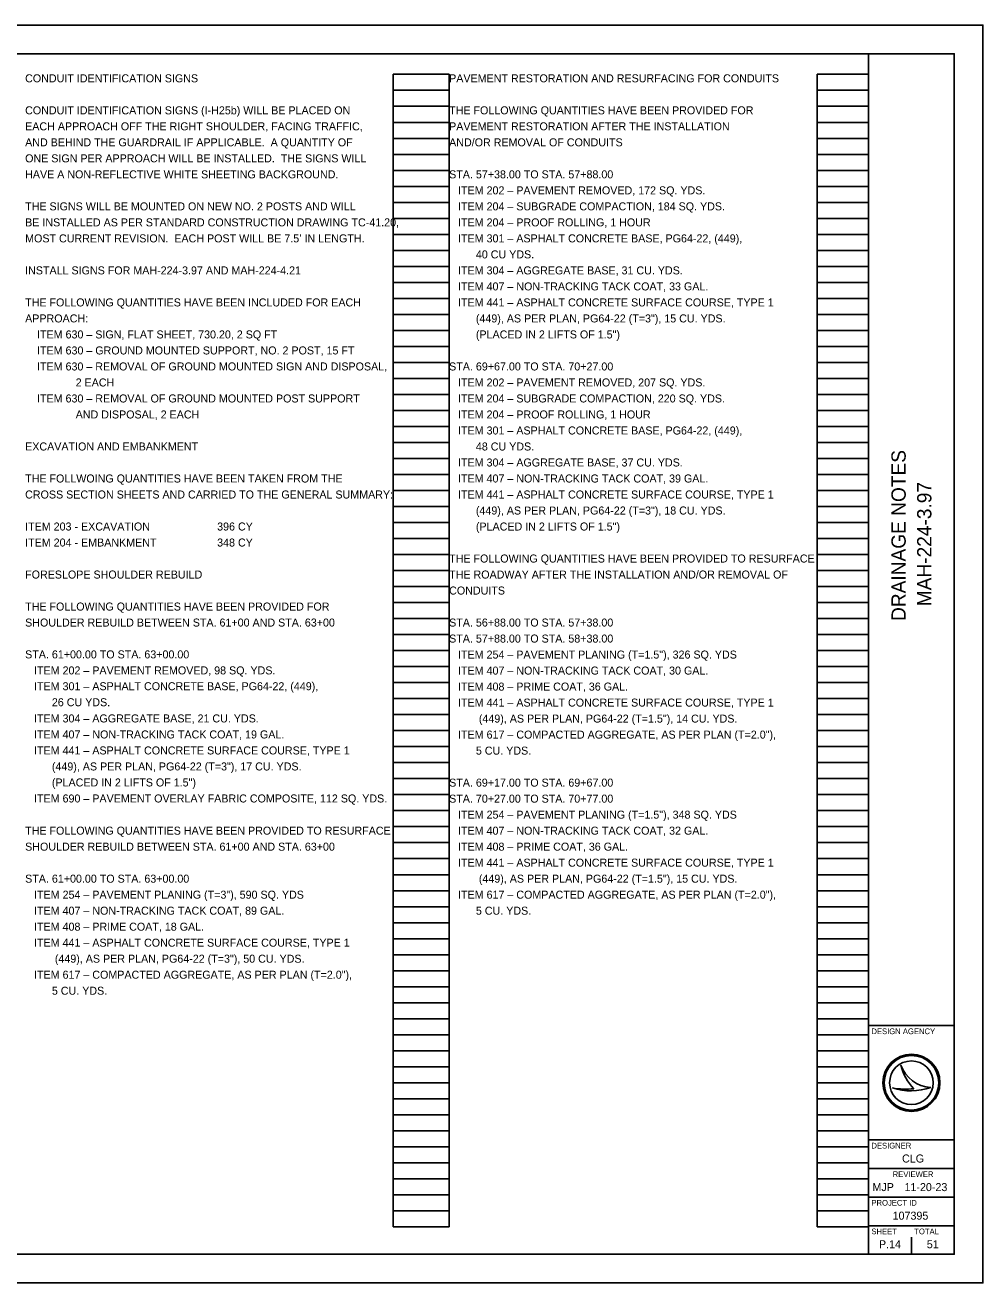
# Model space of a CAD drawing. Extents: x 0 to 34, y 0 to 22.
# Drawn here: x 17.24 to 34, y 0 to 22 of the extents above; entities that cross this region are included whole.
import ezdxf

# ---------------------------------------------------------------- set-up
doc = ezdxf.new("R2010")
doc.units = 0
for name, color, linetype in [('SH_Border', 7, 'Continuous'), ('SH_Cut_Line', 7, 'Continuous'), ('SH_Data', 7, 'Continuous'), ('SH_Text', 7, 'Continuous')]:
    doc.layers.add(name, color=color, linetype=linetype)

msp = doc.modelspace()

# ---------------------------------------------------------------- linework, layer by layer
at = {"layer": 'SH_Border'}
for p, q in [((32, 0.5), (32, 21.5)), ((32, 4.5), (33.5, 4.5)), ((32, 2.5), (33.5, 2.5)), ((32, 2), (33.5, 2)), ((32, 1.5), (33.5, 1.5)), ((32, 1), (33.5, 1))]:
    msp.add_line(p, q, dxfattribs=at)
msp.add_lwpolyline([(1.5, 21.5), (33.5, 21.5), (33.5, 0.5), (1.5, 0.5)], close=True, dxfattribs=at)
at = {"layer": 'SH_Cut_Line'}
msp.add_lwpolyline([(0, 0), (34, 0), (34, 22), (0, 22)], close=True, dxfattribs=at)
at = {"layer": 'SH_Data'}
for p, q in [((23.68, 0.98), (23.68, 21.14)), ((23.68, 21.14), (24.66, 21.14)), ((24.66, 0.98), (24.66, 21.14)), ((31.1, 0.98), (31.1, 21.14)), ((31.1, 21.14), (32, 21.14)), ((32, 0.98), (32, 21.14)), ((23.68, 20.86), (24.66, 20.86)), ((31.1, 20.86), (32, 20.86)), ((23.68, 20.58), (24.66, 20.58)), ((31.1, 20.58), (32, 20.58)), ((23.68, 20.3), (24.66, 20.3)), ((31.1, 20.3), (32, 20.3)), ((23.68, 20.02), (24.66, 20.02)), ((31.1, 20.02), (32, 20.02)), ((23.68, 19.74), (24.66, 19.74)), ((31.1, 19.74), (32, 19.74)), ((23.68, 19.46), (24.66, 19.46)), ((31.1, 19.46), (32, 19.46)), ((23.68, 19.18), (24.66, 19.18)), ((31.1, 19.18), (32, 19.18)), ((23.68, 18.9), (24.66, 18.9)), ((31.1, 18.9), (32, 18.9)), ((23.68, 18.62), (24.66, 18.62)), ((31.1, 18.62), (32, 18.62)), ((23.68, 18.34), (24.66, 18.34)), ((31.1, 18.34), (32, 18.34)), ((23.68, 18.06), (24.66, 18.06)), ((31.1, 18.06), (32, 18.06)), ((23.68, 17.78), (24.66, 17.78)), ((31.1, 17.78), (32, 17.78)), ((23.68, 17.5), (24.66, 17.5)), ((31.1, 17.5), (32, 17.5)), ((23.68, 17.22), (24.66, 17.22)), ((31.1, 17.22), (32, 17.22)), ((23.68, 16.94), (24.66, 16.94)), ((31.1, 16.94), (32, 16.94)), ((23.68, 16.66), (24.66, 16.66)), ((31.1, 16.66), (32, 16.66)), ((23.68, 16.38), (24.66, 16.38)), ((31.1, 16.38), (32, 16.38)), ((23.68, 16.1), (24.66, 16.1)), ((31.1, 16.1), (32, 16.1)), ((23.68, 15.82), (24.66, 15.82)), ((31.1, 15.82), (32, 15.82)), ((23.68, 15.54), (24.66, 15.54)), ((31.1, 15.54), (32, 15.54)), ((23.68, 15.26), (24.66, 15.26)), ((31.1, 15.26), (32, 15.26)), ((23.68, 14.98), (24.66, 14.98)), ((31.1, 14.98), (32, 14.98)), ((23.68, 14.7), (24.66, 14.7)), ((31.1, 14.7), (32, 14.7)), ((23.68, 14.42), (24.66, 14.42)), ((31.1, 14.42), (32, 14.42)), ((23.68, 14.14), (24.66, 14.14)), ((31.1, 14.14), (32, 14.14)), ((23.68, 13.86), (24.66, 13.86)), ((31.1, 13.86), (32, 13.86)), ((23.68, 13.58), (24.66, 13.58)), ((31.1, 13.58), (32, 13.58)), ((23.68, 13.3), (24.66, 13.3)), ((31.1, 13.3), (32, 13.3)), ((23.68, 13.02), (24.66, 13.02)), ((31.1, 13.02), (32, 13.02)), ((23.68, 12.74), (24.66, 12.74)), ((31.1, 12.74), (32, 12.74)), ((23.68, 12.46), (24.66, 12.46)), ((31.1, 12.46), (32, 12.46)), ((23.68, 12.18), (24.66, 12.18)), ((31.1, 12.18), (32, 12.18)), ((23.68, 11.9), (24.66, 11.9)), ((31.1, 11.9), (32, 11.9)), ((23.68, 11.62), (24.66, 11.62)), ((31.1, 11.62), (32, 11.62)), ((23.68, 11.34), (24.66, 11.34)), ((31.1, 11.34), (32, 11.34)), ((23.68, 11.06), (24.66, 11.06)), ((31.1, 11.06), (32, 11.06)), ((23.68, 10.78), (24.66, 10.78)), ((31.1, 10.78), (32, 10.78)), ((23.68, 10.5), (24.66, 10.5)), ((31.1, 10.5), (32, 10.5)), ((23.68, 10.22), (24.66, 10.22)), ((31.1, 10.22), (32, 10.22)), ((23.68, 9.94), (24.66, 9.94)), ((31.1, 9.94), (32, 9.94)), ((23.68, 9.66), (24.66, 9.66)), ((31.1, 9.66), (32, 9.66)), ((23.68, 9.38), (24.66, 9.38)), ((31.1, 9.38), (32, 9.38)), ((23.68, 9.1), (24.66, 9.1)), ((31.1, 9.1), (32, 9.1)), ((23.68, 8.82), (24.66, 8.82)), ((31.1, 8.82), (32, 8.82)), ((23.68, 8.54), (24.66, 8.54)), ((31.1, 8.54), (32, 8.54)), ((23.68, 8.26), (24.66, 8.26)), ((31.1, 8.26), (32, 8.26)), ((23.68, 7.98), (24.66, 7.98)), ((31.1, 7.98), (32, 7.98)), ((23.68, 7.7), (24.66, 7.7)), ((31.1, 7.7), (32, 7.7)), ((23.68, 7.42), (24.66, 7.42)), ((31.1, 7.42), (32, 7.42)), ((23.68, 7.14), (24.66, 7.14)), ((31.1, 7.14), (32, 7.14)), ((23.68, 6.86), (24.66, 6.86)), ((31.1, 6.86), (32, 6.86)), ((23.68, 6.58), (24.66, 6.58)), ((31.1, 6.58), (32, 6.58)), ((23.68, 6.3), (24.66, 6.3)), ((31.1, 6.3), (32, 6.3)), ((23.68, 6.02), (24.66, 6.02)), ((31.1, 6.02), (32, 6.02)), ((23.68, 5.74), (24.66, 5.74)), ((31.1, 5.74), (32, 5.74)), ((23.68, 5.46), (24.66, 5.46)), ((31.1, 5.46), (32, 5.46)), ((23.68, 5.18), (24.66, 5.18)), ((31.1, 5.18), (32, 5.18)), ((23.68, 4.9), (24.66, 4.9)), ((31.1, 4.9), (32, 4.9)), ((23.68, 4.62), (24.66, 4.62)), ((31.1, 4.62), (32, 4.62)), ((23.68, 4.34), (24.66, 4.34)), ((31.1, 4.34), (32, 4.34)), ((23.68, 4.06), (24.66, 4.06)), ((31.1, 4.06), (32, 4.06)), ((23.68, 3.78), (24.66, 3.78)), ((31.1, 3.78), (32, 3.78)), ((32.567, 3.81), (32.567, 3.81)), ((23.68, 3.5), (24.66, 3.5)), ((31.1, 3.5), (32, 3.5)), ((32.417, 3.41), (32.417, 3.41)), ((32.75, 3.5), (32.75, 3.5)), ((33.087, 3.419), (33.087, 3.419)), ((23.68, 3.22), (24.66, 3.22)), ((31.1, 3.22), (32, 3.22)), ((23.68, 2.94), (24.66, 2.94)), ((31.1, 2.94), (32, 2.94)), ((23.68, 2.66), (24.66, 2.66)), ((31.1, 2.66), (32, 2.66)), ((23.68, 2.38), (24.66, 2.38)), ((31.1, 2.38), (32, 2.38)), ((23.68, 2.1), (24.66, 2.1)), ((31.1, 2.1), (32, 2.1)), ((23.68, 1.82), (24.66, 1.82)), ((31.1, 1.82), (32, 1.82)), ((23.68, 1.54), (24.66, 1.54)), ((31.1, 1.54), (32, 1.54)), ((23.68, 1.26), (24.66, 1.26)), ((31.1, 1.26), (32, 1.26)), ((23.68, 0.98), (24.66, 0.98)), ((31.1, 0.98), (32, 0.98)), ((32.375, 0.675), (32.375, 0.675)), ((32.75, 0.5), (32.75, 0.8))]:
    msp.add_line(p, q, dxfattribs=at)
for radius in [0.5, 0.477, 0.477, 0.382]:
    msp.add_circle((32.75, 3.5), radius, dxfattribs=at)
for centre, radius, start, end in [((33.116, 3.998), 0.58, 198.9257, 198.9319), ((33.347, 3.97), 0.796, 191.6379, 191.6421), ((33.116, 3.998), 0.58, 198.9319, 267.1657), ((33.347, 3.97), 0.796, 191.6421, 226.0947), ((32.739, 4.37), 1.013, 251.4576, 290.0832), ((32.648, 4.654), 1.266, 259.4964, 259.4995), ((32.739, 4.37), 1.013, 251.4527, 251.4576), ((32.648, 4.654), 1.266, 259.4995, 276.6672)]:
    msp.add_arc(centre, radius, start, end, dxfattribs=at)

# ---------------------------------------------------------------- texts
for s, p in [('DRAINAGE NOTES', (32.65, 11.578)), ('MAH-224-3.97', (33.1, 11.835))]:
    msp.add_text(s, height=0.25, rotation=90, dxfattribs=at).set_placement(p)
for s, height, p in [('DESIGN AGENCY', 0.1, (32.05, 4.35)), ('DESIGNER', 0.1, (32.05, 2.35)), ('CLG', 0.14, (32.586, 2.105)), ('REVIEWER', 0.1, (32.422, 1.85)), ('MJP', 0.14, (32.068, 1.605)), ('11-20-23', 0.14, (32.629, 1.605)), ('PROJECT ID', 0.1, (32.05, 1.35)), ('107395', 0.14, (32.421, 1.105)), ('SHEET', 0.1, (32.05, 0.85)), ('TOTAL', 0.1, (32.8, 0.85)), ('P.14', 0.14, (32.182, 0.605)), ('51', 0.14, (33.019, 0.605))]:
    msp.add_text(s, height=height, dxfattribs=at).set_placement(p)
at = {"layer": 'SH_Text'}
for s, p in [('CONDUIT IDENTIFICATION SIGNS', (17.24, 21)), ('PAVEMENT RESTORATION AND RESURFACING FOR CONDUITS', (24.66, 21)), ('CONDUIT IDENTIFICATION SIGNS (I-H25b) WILL BE PLACED ON', (17.24, 20.44)), ('THE FOLLOWING QUANTITIES HAVE BEEN PROVIDED FOR', (24.66, 20.44)), ('EACH APPROACH OFF THE RIGHT SHOULDER, FACING TRAFFIC,', (17.24, 20.16)), ('PAVEMENT RESTORATION AFTER THE INSTALLATION', (24.66, 20.16)), ('AND BEHIND THE GUARDRAIL IF APPLICABLE.  A QUANTITY OF', (17.24, 19.88)), ('AND/OR REMOVAL OF CONDUITS', (24.66, 19.88)), ('ONE SIGN PER APPROACH WILL BE INSTALLED.  THE SIGNS WILL', (17.24, 19.6)), ('HAVE A NON-REFLECTIVE WHITE SHEETING BACKGROUND.', (17.24, 19.32)), ('STA. 57+38.00 TO STA. 57+88.00', (24.66, 19.32)), ('   ITEM 202 – PAVEMENT REMOVED, 172 SQ. YDS.', (24.66, 19.04)), ('THE SIGNS WILL BE MOUNTED ON NEW NO. 2 POSTS AND WILL', (17.24, 18.76)), ('   ITEM 204 – SUBGRADE COMPACTION, 184 SQ. YDS.', (24.66, 18.76)), ('BE INSTALLED AS PER STANDARD CONSTRUCTION DRAWING TC-41.20,', (17.24, 18.48)), ('   ITEM 204 – PROOF ROLLING, 1 HOUR', (24.66, 18.48)), ('MOST CURRENT REVISION.  EACH POST WILL BE 7.5’ IN LENGTH.', (17.24, 18.2)), ('   ITEM 301 – ASPHALT CONCRETE BASE, PG64-22, (449),', (24.66, 18.2)), ('         40 CU YDS.', (24.66, 17.92)), ('INSTALL SIGNS FOR MAH-224-3.97 AND MAH-224-4.21', (17.24, 17.64)), ('   ITEM 304 – AGGREGATE BASE, 31 CU. YDS.', (24.66, 17.64)), ('   ITEM 407 – NON-TRACKING TACK COAT, 33 GAL.', (24.66, 17.36)), ('THE FOLLOWING QUANTITIES HAVE BEEN INCLUDED FOR EACH', (17.24, 17.08)), ('   ITEM 441 – ASPHALT CONCRETE SURFACE COURSE, TYPE 1', (24.66, 17.08)), ('APPROACH:', (17.24, 16.8)), ('         (449), AS PER PLAN, PG64-22 (T=3"), 15 CU. YDS.', (24.66, 16.8)), ('    ITEM 630 – SIGN, FLAT SHEET, 730.20, 2 SQ FT', (17.24, 16.52)), ('         (PLACED IN 2 LIFTS OF 1.5")', (24.66, 16.52)), ('    ITEM 630 – GROUND MOUNTED SUPPORT, NO. 2 POST, 15 FT', (17.24, 16.24)), ('    ITEM 630 – REMOVAL OF GROUND MOUNTED SIGN AND DISPOSAL,', (17.24, 15.96)), ('STA. 69+67.00 TO STA. 70+27.00', (24.66, 15.96)), ('                 2 EACH', (17.24, 15.68)), ('   ITEM 202 – PAVEMENT REMOVED, 207 SQ. YDS.', (24.66, 15.68)), ('    ITEM 630 – REMOVAL OF GROUND MOUNTED POST SUPPORT', (17.24, 15.4)), ('   ITEM 204 – SUBGRADE COMPACTION, 220 SQ. YDS.', (24.66, 15.4)), ('                 AND DISPOSAL, 2 EACH', (17.24, 15.12)), ('   ITEM 204 – PROOF ROLLING, 1 HOUR', (24.66, 15.12)), ('   ITEM 301 – ASPHALT CONCRETE BASE, PG64-22, (449),', (24.66, 14.84)), ('EXCAVATION AND EMBANKMENT', (17.24, 14.56)), ('         48 CU YDS.', (24.66, 14.56)), ('   ITEM 304 – AGGREGATE BASE, 37 CU. YDS.', (24.66, 14.28)), ('THE FOLLWOING QUANTITIES HAVE BEEN TAKEN FROM THE', (17.24, 14)), ('   ITEM 407 – NON-TRACKING TACK COAT, 39 GAL.', (24.66, 14)), ('CROSS SECTION SHEETS AND CARRIED TO THE GENERAL SUMMARY:', (17.24, 13.72)), ('   ITEM 441 – ASPHALT CONCRETE SURFACE COURSE, TYPE 1', (24.66, 13.72)), ('         (449), AS PER PLAN, PG64-22 (T=3"), 18 CU. YDS.', (24.66, 13.44)), ('ITEM 203 - EXCAVATION', (17.24, 13.16)), ('396 CY', (20.6, 13.16)), ('         (PLACED IN 2 LIFTS OF 1.5")', (24.66, 13.16)), ('ITEM 204 - EMBANKMENT', (17.24, 12.88)), ('348 CY', (20.6, 12.88)), ('THE FOLLOWING QUANTITIES HAVE BEEN PROVIDED TO RESURFACE', (24.66, 12.6)), ('FORESLOPE SHOULDER REBUILD', (17.24, 12.32)), ('THE ROADWAY AFTER THE INSTALLATION AND/OR REMOVAL OF', (24.66, 12.32)), ('CONDUITS', (24.66, 12.04)), ('THE FOLLOWING QUANTITIES HAVE BEEN PROVIDED FOR', (17.24, 11.76)), ('SHOULDER REBUILD BETWEEN STA. 61+00 AND STA. 63+00', (17.24, 11.48)), ('STA. 56+88.00 TO STA. 57+38.00', (24.66, 11.48)), ('STA. 57+88.00 TO STA. 58+38.00', (24.66, 11.2)), ('STA. 61+00.00 TO STA. 63+00.00', (17.24, 10.923)), ('   ITEM 254 – PAVEMENT PLANING (T=1.5"), 326 SQ. YDS', (24.66, 10.92)), ('   ITEM 202 – PAVEMENT REMOVED, 98 SQ. YDS.', (17.24, 10.643)), ('   ITEM 407 – NON-TRACKING TACK COAT, 30 GAL.', (24.66, 10.64)), ('   ITEM 301 – ASPHALT CONCRETE BASE, PG64-22, (449),', (17.24, 10.366)), ('   ITEM 408 – PRIME COAT, 36 GAL.', (24.66, 10.36)), ('         26 CU YDS.', (17.24, 10.086)), ('   ITEM 441 – ASPHALT CONCRETE SURFACE COURSE, TYPE 1', (24.66, 10.08)), ('   ITEM 304 – AGGREGATE BASE, 21 CU. YDS.', (17.24, 9.803)), ('          (449), AS PER PLAN, PG64-22 (T=1.5"), 14 CU. YDS.', (24.66, 9.8)), ('   ITEM 407 – NON-TRACKING TACK COAT, 19 GAL.', (17.24, 9.523)), ('   ITEM 617 – COMPACTED AGGREGATE, AS PER PLAN (T=2.0"),', (24.66, 9.52)), ('   ITEM 441 – ASPHALT CONCRETE SURFACE COURSE, TYPE 1', (17.24, 9.243)), ('         5 CU. YDS.', (24.66, 9.24)), ('         (449), AS PER PLAN, PG64-22 (T=3"), 17 CU. YDS.', (17.24, 8.963)), ('         (PLACED IN 2 LIFTS OF 1.5")', (17.24, 8.683)), ('STA. 69+17.00 TO STA. 69+67.00', (24.66, 8.68)), ('   ITEM 690 – PAVEMENT OVERLAY FABRIC COMPOSITE, 112 SQ. YDS.', (17.24, 8.403)), ('STA. 70+27.00 TO STA. 70+77.00', (24.66, 8.4)), ('   ITEM 254 – PAVEMENT PLANING (T=1.5"), 348 SQ. YDS', (24.66, 8.12)), ('THE FOLLOWING QUANTITIES HAVE BEEN PROVIDED TO RESURFACE', (17.24, 7.84)), ('   ITEM 407 – NON-TRACKING TACK COAT, 32 GAL.', (24.66, 7.84)), ('SHOULDER REBUILD BETWEEN STA. 61+00 AND STA. 63+00', (17.24, 7.56)), ('   ITEM 408 – PRIME COAT, 36 GAL.', (24.66, 7.56)), ('   ITEM 441 – ASPHALT CONCRETE SURFACE COURSE, TYPE 1', (24.66, 7.28)), ('STA. 61+00.00 TO STA. 63+00.00', (17.24, 7)), ('          (449), AS PER PLAN, PG64-22 (T=1.5"), 15 CU. YDS.', (24.66, 7)), ('   ITEM 254 – PAVEMENT PLANING (T=3"), 590 SQ. YDS', (17.24, 6.72)), ('   ITEM 617 – COMPACTED AGGREGATE, AS PER PLAN (T=2.0"),', (24.66, 6.72)), ('   ITEM 407 – NON-TRACKING TACK COAT, 89 GAL.', (17.24, 6.44)), ('         5 CU. YDS.', (24.66, 6.44)), ('   ITEM 408 – PRIME COAT, 18 GAL.', (17.24, 6.16)), ('   ITEM 441 – ASPHALT CONCRETE SURFACE COURSE, TYPE 1', (17.24, 5.88)), ('          (449), AS PER PLAN, PG64-22 (T=3"), 50 CU. YDS.', (17.24, 5.6)), ('   ITEM 617 – COMPACTED AGGREGATE, AS PER PLAN (T=2.0"),', (17.24, 5.32)), ('         5 CU. YDS.', (17.24, 5.04))]:
    msp.add_text(s, height=0.14, dxfattribs=at).set_placement(p)

doc.saveas('drawing.dxf')
